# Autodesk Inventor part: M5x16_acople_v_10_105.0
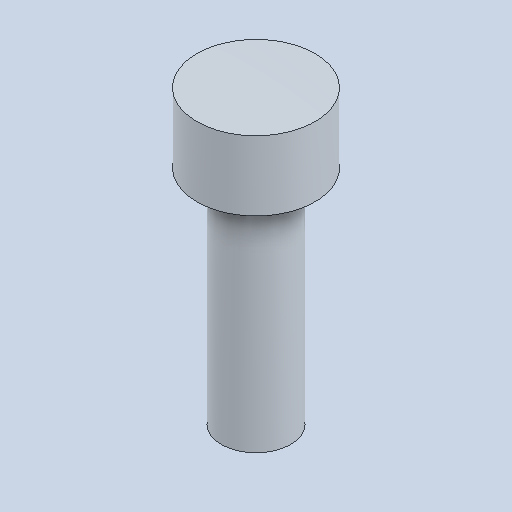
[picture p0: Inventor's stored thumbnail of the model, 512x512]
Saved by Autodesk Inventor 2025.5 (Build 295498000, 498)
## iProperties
Created: 2026-10
Part Number: M5x16_acople_v_10_105.0
Material: Genérico
Document SubType Name: Modeling
Designer: Luis M
Density: 1 g/cm^3
Appearance: Valor por defecto
Author: Luis M
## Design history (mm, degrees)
feature "Base1"
node "Sólido1"
